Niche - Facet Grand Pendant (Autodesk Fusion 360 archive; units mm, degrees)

design "Facet Grand" references "PCB Single Pendant Canopy"
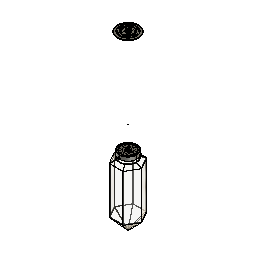
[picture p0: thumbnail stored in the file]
base_feature "Base Feature" bodies "Glass-Facet Grand"
external_derived "ExternalDerived1" bodies "Set Screw", "Strain Relief", "Lead-1", "Lead-2", "Lead-2.1", "Lead-1.1", "Coax", "Stem"
move "Move1"
move "Move2"
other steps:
derived_base_feature "Derived Base Feature" bodies "Set Screw", "Strain Relief", "Lead-1", "Lead-2", "Lead-2.1", "Lead-1.1", "Coax", "Stem"
create_component "CreateComponent1"
named bodies: "Glass-Facet Grand", "Set Screw", "Strain Relief", "Lead-1", "Lead-2", "Lead-2.1", "Lead-1.1", "Coax", "Stem", "Strain Relief Cap", "Nylon Gripper (2)", "Cap", "Thumbscrew (1)", "Thumbscrew (2)", "Thumbscrew (3)", "Niche-PCB", "FJ-Plug Cover", "FJ-Plug", "FJ-Plug1.1", "FJ-Plug1.2", "FJ-Plug1.3", "Fj-Plug1.4", "Canopy", "FJ-Port", "FJ-Port1.1", "Spacer", "Universal Mount", "FJ-Port Cover", "Diffuser"

design "FJ Plug - PCB-Hardware"
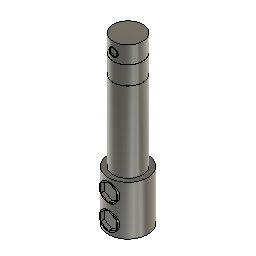
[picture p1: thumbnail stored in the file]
sketch "Sketch1" plane through (0, 0, 0) normal (0, 0, 1) x axis (1, 0, 0)
  circle C1 centre (0, 0) radius 3.048
  point P1 (0, 0)
  point P2 (0, 0)
  coincident P1 P2
  dimension "d1" diameter C1 = 6.096
extrude "Extrude1" new body sketch "Sketch1" along normal blind 34.036
sketch "Sketch2" plane through (0, 0, 0) normal (0, 0, 1) x axis (1, 0, 0)
  circle C1 centre (0, 0) radius 4.064
  point P1 (0, 0)
  point P2 (0, 0)
  coincident P1 P2
  dimension "d4" diameter C1 = 8.128
extrude "Extrude2" add sketch "Sketch2" along normal blind 10.16
sketch "Sketch3" plane through (0, 0, 0) normal (0, 1, 0) x axis (1, 0, 0)
  line L1 (6.35, 0) -> (-6.35, 0)
  line L2 (6.35, -30.48) -> (-6.35, -30.48)
  line L3 (2.54, -30.48) -> (6.35, -30.48)
  line L4 (2.54, -26.67) -> (2.54, -30.48)
  line L5 (6.35, -26.67) -> (2.54, -26.67)
  line L6 (6.35, -30.48) -> (6.35, -26.67)
  horizontal L1
  horizontal L3
  vertical L4
  horizontal L5
  vertical L6
  dimension "d7" = 30.48
revolve "Revolve1" sketch "Sketch3" AlongAngle 360
sketch "Sketch4" plane through (0, 0, 0) normal (0, 1, 0) x axis (1, 0, 0)
  line L1 (2.54, -30.48) -> (3.048, -30.48)
  line L2 (2.54, -26.67) -> (2.54, -30.48)
  line L3 (3.048, -26.67) -> (2.54, -26.67)
  line L4 (3.048, -30.48) -> (3.048, -26.67)
  horizontal L1
  vertical L2
  horizontal L3
  vertical L4
revolve "Revolve2" sketch "Sketch4" AlongAngle 360
chamfer "Chamfer1" distance 0.0254
chamfer "Chamfer2" distance 0.0254
hole "Hole1" HoleDepth 33.401 HoleDiameter 4.826 TipAngle 180
hole "Hole2" HoleDepth 3.81 HoleDiameter 1.778 TipAngle 180
hole "Hole3" HoleDepth 3.81 HoleDiameter 3.81 TipAngle 180
hole "Hole4" HoleDepth 3.81 HoleDiameter 3.81 TipAngle 180
sketch "Sketch5" plane through (0, 0, 0) normal (0, 1, 0) x axis (1, 0, 0)
  circle C1 centre (0, -32.0802) radius 0.889
  dimension "d24" diameter C1 = 1.778
extrude "Extrude3" new body sketch "Sketch5" along normal blind 1.778
move "Move1"
sketch "Sketch6" plane through (0, -3.048, 0) normal (0, -1, 0) x axis (1, 0, 0)
  line L1 (0.7259, 31.6611) -> (0, 31.242)
  line L2 (0.7259, 32.4993) -> (0.7259, 31.6611)
  line L3 (0, 32.9184) -> (0.7259, 32.4993)
  line L4 (-0.7259, 32.4993) -> (0, 32.9184)
  line L5 (-0.7259, 31.6611) -> (-0.7259, 32.4993)
  line L6 (0, 31.242) -> (-0.7259, 31.6611)
  circle C1 centre (0, 32.0802) radius 0.889
  point P2 (0, 32.0802)
  point P9 (0, 32.0802)
  coincident P2 P9
extrude "Extrude4" cut sketch "Sketch6" profile of L1 L2 L3 L4 L5 L6 against normal blind 0.254
sketch "Sketch7" plane through (0, 0, 0) normal (0, 1, 0) x axis (1, 0, 0)
  circle C1 centre (0, -2.4384) radius 1.905
  circle C2 centre (0, -7.5565) radius 1.905
  dimension "d29" diameter C1 = 3.81
  dimension "d30" diameter C2 = 3.81
extrude "Extrude5" new body sketch "Sketch7" profile of C2 along normal blind 3.81
move "Move2"
sketch "Sketch8" plane through (0, -4.064, 0) normal (0, -1, 0) x axis (1, 0, 0)
  line L1 (1.5948, 6.6357) -> (0, 5.715)
  line L2 (1.5948, 8.4772) -> (1.5948, 6.6357)
  line L3 (0, 9.398) -> (1.5948, 8.4772)
  line L4 (-1.5948, 8.4772) -> (0, 9.398)
  line L5 (-1.5948, 6.6357) -> (-1.5948, 8.4772)
  line L6 (0, 5.715) -> (-1.5948, 6.6357)
  circle C1 centre (0, 7.5565) radius 1.905
  point P2 (0, 7.5565)
  point P9 (0, 7.5565)
  coincident P2 P9
extrude "Extrude6" cut sketch "Sketch8" profile of L1 L2 L3 L4 L5 L6 against normal blind 0.762
copy_paste_bodies "CopyPasteBodies2"
move "Move4"
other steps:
base_feature "Base Feature"

design "Flask Petite"
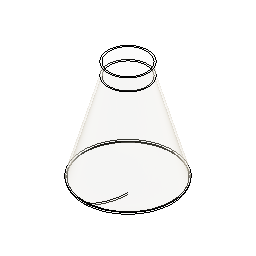
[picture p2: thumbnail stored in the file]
sketch "Sketch1" plane through (0, 0, 0) normal (1, 0, 0) x axis (0, 1, 0)
canvas "Canvas1"
sketch "Sketch2" plane through (0, 0, 0) normal (1, 0, 0) x axis (0, 1, 0)
  line L1 (-5.314, 187.093) -> (-57.384, 187.093)
  line L2 (-57.384, 155.343) -> (-57.384, 187.093)
  line L3 (-121.92, -71.12) -> (-57.384, 155.343)
  line L4 (-5.314, -112.5919) -> (-5.314, 187.093)
  curve K1 (-5.314, -112.5919) -> (-121.92, -74.8854)
  arc A1 centre (-115.3135, -73.0027) radius 6.8695 clockwise from (-121.92, -74.8854) to (-121.92, -71.12)
  point P2 (-57.384, 187.093)
  point P3 (-5.314, 187.093)
  point P4 (-57.384, 155.343)
  horizontal L1
  perpendicular L1 L2
  tangent L3 A1
  perpendicular L1 L4
  dimension "d1" distance P2 P3 = 52.07
  dimension "d2" distance P2 P4 = 31.75
revolve "Revolve1" sketch "Sketch2" AlongAngle 360
fillet "Fillet1" radius 5.08
shell "Shell1" innerThickness 4

design "PCB Single Pendant Canopy" references "Diffuser", "PCB Cap", "Flask Petite", "FJ Cover - PCB-Hardware", "PCB Canopy", "FJ Plug - PCB-Hardware"
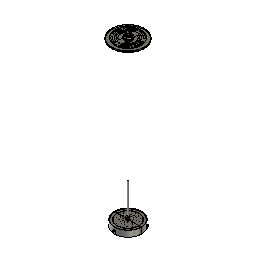
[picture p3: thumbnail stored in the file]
external_derived "ExternalDerived1" bodies "Nylon Gripper", "Set Screw", "Strain Relief", "Lead-1", "Lead-2", "Lead-2.1", "Lead-1.1", "Coax"
external_derived "ExternalDerived2" bodies "FJ-Plug Cover"
move "Move1"
move "Move2" TranslateX 3.175 TranslateY 0.254 TranslateZ 0
move "Move3" TranslateX 0 TranslateY 0 TranslateZ 1092.2
external_derived "ExternalDerived3" bodies "FJ-Plug", "FJ-Plug1.2", "FJ-Plug1.1", "FJ-Plug1.3", "Fj-Plug1.4"
move "Move4" TranslateX 0 TranslateY 0 TranslateZ 1117.6
external_derived "ExternalDerived4" bodies "Nylon Gripper", "Spacer", "Canopy", "FJ-Port", "FJ-Port1.1", "Universal Mount", "FJ-Port Cover", "Lead-1.1"
move "Move5"
move "Move6"
external_derived "ExternalDerived5" bodies "Diffuser"
move "Move7"
external_derived "ExternalDerived6" bodies "Thumbscrew (1)"
align "Align1"
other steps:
derived_base_feature "Derived Base Feature1"
derived_base_feature "Derived Base Feature2" bodies "FJ-Plug Cover"
derived_base_feature "Derived Base Feature3" bodies "FJ-Plug", "FJ-Plug1.1", "FJ-Plug1.2"
derived_base_feature "Derived Base Feature4" bodies "Body1 (1)", "Body1 (1) (1)", "Body2 (1)", "Body1 (2)", "Body1 (3)", "Body1 (4)", "Canopy", "FJ-Port"
derived_base_feature "Derived Base Feature5" bodies "Diffuser"
derived_base_feature "Derived Base Feature6" bodies "Body1", "Thumbscrew (1)"
named bodies: "Nylon Gripper", "Set Screw", "Strain Relief", "Lead-1", "Lead-2", "Lead-2.1", "Lead-1.1", "Coax", "Stem", "stem (2)", "Strain Relief Cap", "Nylon Gripper (2)", "Cap", "Thumbscrew (1)", "Thumbscrew (2)", "Thumbscrew (3)", "Niche-PCB", "FJ-Plug Cover", "FJ-Plug", "FJ-Plug1.1", "FJ-Plug1.2", "FJ-Plug1.3", "Fj-Plug1.4", "Body1 (1)", "Body1 (1) (1)", "Body2 (1)", "Body1 (2)", "Body1 (3)", "Body1 (4)", "Canopy", "FJ-Port", "FJ-Port1.1", "Spacer", "Universal Mount", "FJ-Port Cover", "Diffuser", "Body1"

design "FJ Female"
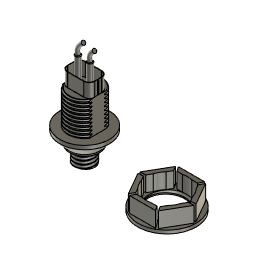
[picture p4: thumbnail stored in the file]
sketch "Sketch1" plane through (0, 0, 0) normal (0, 0, 1) x axis (1, 0, 0)
  circle C1 centre (0, 0) radius 4.445
  point P1 (0, 0)
  point P2 (0, 0)
  coincident P1 P2
  dimension "d1" diameter C1 = 8.89
extrude "Extrude1" new body sketch "Sketch1" along normal blind 6.858
sketch "Sketch2" plane through (0, 0, 6.858) normal (0, 0, 1) x axis (-1, 0, 0)
  circle C1 centre (0, 0) radius 4.445
  circle C2 centre (0, 0) radius 6.985
  point P1 (0, 0)
  point P3 (0, 0)
  coincident P1 P3
  dimension "d4" diameter C2 = 13.97
extrude "Extrude2" add sketch "Sketch2" along normal blind 1.27
work_plane "WorkPlane1" AlongDistance 5.08
sketch "Sketch3" plane through (0, 0, 13.208) normal (0, 0, 1) x axis (1, 0, 0)
  circle C1 centre (0, 0) radius 11.43
  point P1 (0, 0)
  point P2 (0, 0)
  coincident P1 P2
  dimension "d8" diameter C1 = 22.86
loft "Loft1" sketch "Sketch3"
extrude "Extrude3" add of existing geometry blind 1.778
sketch "Sketch4" plane through (0, 0, 14.986) normal (0, 0, 1) x axis (-1, 0, 0)
  circle C1 centre (0, 0) radius 11.43
  circle C2 centre (0, 0) radius 7.62
  point P1 (0, 0)
  point P3 (0, 0)
  coincident P1 P3
  dimension "d11" diameter C2 = 15.24
extrude "Extrude4" add sketch "Sketch4" profile of C2 along normal blind 15.24
sketch "Sketch5" plane through (0, 0, 30.226) normal (0, 0, 1) x axis (-1, 0, 0)
  line L1 (6.35, 0) -> (0, 0)
  line L2 (-6.35, 0) -> (0, 0)
  line L3 (6.35, -4.2121) -> (6.35, 0)
  line L4 (6.35, 4.2121) -> (6.35, 0)
  line L5 (-6.35, -4.2121) -> (-6.35, 0)
  line L6 (-6.35, 4.2121) -> (-6.35, 0)
  circle C1 centre (0, 0) radius 7.62
  point P2 (0, 0)
  point P3 (0, 0)
  point P5 (0, 0)
  point P7 (6.35, -4.2121)
  point P8 (6.35, 4.2121)
  point P9 (-6.35, -4.2121)
  point P10 (-6.35, 0)
  point P11 (-6.35, 4.2121)
  point P4 (6.35, 0)
  point P6 (-6.35, 0)
  coincident P2 P3
  horizontal L1
  coincident P2 P5
  parallel L1 L2
  coincident C1 P7
  perpendicular L1 L3
  coincident C1 P8
  perpendicular L1 L4
  coincident C1 P9
  perpendicular L2 L5
  coincident L2 P10
  perpendicular L2 L6
  coincident C1 P11
  dimension "d14" distance P3 P4 = 6.35
  dimension "d15" distance P5 P6 = 6.35
extrude "Extrude5" cut sketch "Sketch5" profile of C1 L3 L4 L5 L6 against normal blind 15.24
sketch "Sketch6" plane through (0, 0, 30.226) normal (0, 0, 1) x axis (-1, 0, 0)
  line L1 (-6.35, -4.2121) -> (-6.35, 4.2121)
  line L2 (6.35, 4.2121) -> (6.35, -4.2121)
  line L3 (-6.35, -4.2121) -> (6.35, -4.2121)
  line L4 (6.35, 4.2121) -> (-6.35, 4.2121)
  line L5 (6.35, -4.2121) -> (6.35, 4.2121)
  line L6 (-6.35, 4.2121) -> (-6.35, -4.2121)
  line L7 (-6.223, 4.064) -> (6.223, 4.064)
  line L8 (-6.223, -4.064) -> (-6.223, 4.064)
  line L9 (6.223, -4.064) -> (-6.223, -4.064)
  line L10 (6.223, 4.064) -> (6.223, -4.064)
  line L11 (-6.223, -4.064) -> (6.223, 4.064)
  line L12 (6.223, -4.064) -> (-6.223, 4.064)
  arc A1 centre (0, 0) radius 7.62 clockwise from (6.35, -4.2121) to (-6.35, -4.2121)
  arc A2 centre (0, 0) radius 7.62 clockwise from (-6.35, 4.2121) to (6.35, 4.2121)
  point P4 (6.35, -4.2121)
  point P7 (6.35, -4.2121)
  point P3 (-6.35, -4.2121)
  point P8 (-6.35, -4.2121)
  point P2 (-6.35, 4.2121)
  point P9 (-6.35, 4.2121)
  point P6 (6.35, 4.2121)
  point P10 (6.35, 4.2121)
  point P15 (0, 0)
  point P5 (0, 0)
  point P13 (-6.223, -4.064)
  point P14 (6.223, -4.064)
  point P12 (-6.223, 4.064)
  coincident P4 P7
  coincident P3 P8
  coincident P2 P9
  coincident P6 P10
  perpendicular L7 L8
  parallel L7 L9
  parallel L8 L10
  horizontal L7
  coincident L11 P15
  coincident L12 P15
  coincident P5 P15
  dimension "d18" distance P13 P14 = 12.446
  dimension "d19" distance P12 P13 = 8.128
extrude "Extrude6" add sketch "Sketch6" profile of L1 L2 L3 L4 L5 L6 L7 L8 L9 L10 along normal blind 6.35
fillet "Fillet1" radius 2.54
sketch "Sketch7" plane through (6.35, 0, 0) normal (1, 0, 0) x axis (0, 1, 0)
  line L1 (1.6721, 36.576) -> (1.6721, 30.226)
  line L2 (-1.6721, 36.576) -> (1.6721, 36.576)
  line L3 (-1.6721, 30.226) -> (-1.6721, 36.576)
  line L4 (-4.2121, 30.226) -> (-1.6721, 30.226)
  line L5 (-4.2121, 14.986) -> (-4.2121, 30.226)
  line L6 (4.2121, 14.986) -> (-4.2121, 14.986)
  line L7 (4.2121, 30.226) -> (4.2121, 14.986)
  line L8 (1.6721, 30.226) -> (4.2121, 30.226)
  line L9 (0.254, 36.576) -> (-0.2492, 36.576)
  line L10 (0.254, 30.226) -> (0.254, 36.576)
  line L11 (-0.2492, 30.226) -> (0.254, 30.226)
  line L12 (-0.2492, 36.576) -> (-0.2492, 30.226)
  point P10 (-0.2492, 36.576)
  horizontal L9
  vertical L10
  horizontal L11
  vertical L12
  coincident L2 P10
extrude "Extrude7" cut sketch "Sketch7" profile of L2 L9 L10 L11 L12 against normal blind 0.508
thread "Thread1"
fillet "Fillet2" radius 0.635
thread "Thread2"
sketch "Sketch8" plane through (0, 0, 30.226) normal (0, 0, 1) x axis (-1, 0, 0)
  line L1 (-6.223, -1.524) -> (-6.223, -0.254)
  line L2 (3.683, -4.064) -> (-3.683, -4.064)
  line L3 (6.223, 1.524) -> (6.223, -1.524)
  line L4 (-3.683, 4.064) -> (3.683, 4.064)
  line L5 (-6.223, 0.2492) -> (-6.223, 1.524)
  line L6 (-6.35, 0.2492) -> (-6.223, 0.2492)
  line L7 (-6.35, -0.254) -> (-6.35, 0.2492)
  line L8 (-6.223, -0.254) -> (-6.35, -0.254)
  arc A1 centre (-3.683, -1.524) radius 2.54 clockwise from (-3.683, -4.064) to (-6.223, -1.524)
  arc A2 centre (3.683, -1.524) radius 2.54 clockwise from (6.223, -1.524) to (3.683, -4.064)
  arc A3 centre (3.683, 1.524) radius 2.54 clockwise from (3.683, 4.064) to (6.223, 1.524)
  arc A4 centre (-3.683, 1.524) radius 2.54 clockwise from (-6.223, 1.524) to (-3.683, 4.064)
  circle C1 centre (3.048, 0) radius 1.27
  circle C2 centre (-2.54, 0) radius 1.27
  dimension "d26" diameter C1 = 2.54
  dimension "d27" diameter C2 = 2.54
extrude "Extrude8" add sketch "Sketch8" profile of C1 C2 along normal blind 11.43
sketch "Sketch9" plane through (0, 0, 0) normal (0, 1, 0) x axis (1, 0, 0)
  curve K1 (4.572, -46.99) -> (2.54, -41.656)
  curve K2 (-0.508, -47.752) -> (-3.048, -41.656)
pipe "Pipe1" SectionSize 1.778 SectionThickness 0.0762
pipe "Pipe2" SectionSize 1.778 SectionThickness 0.0762
sketch "Sketch10" plane through (0, 0, 0) normal (0, 0, 1) x axis (1, 0, 0)
  circle C1 centre (38.1, 0) radius 13.462
  dimension "d38" diameter C1 = 26.924
extrude "Extrude9" new body sketch "Sketch10" along normal blind 1.524
sketch "Sketch11" plane through (0, 0, 1.524) normal (0, 0, 1) x axis (-1, 0, 0)
  circle C1 centre (-38.1, 0) radius 13.462
  circle C2 centre (-38.1, 0) radius 9.271
  concentric C1 C2
  dimension "d41" diameter C2 = 18.542
extrude "Extrude10" cut sketch "Sketch11" profile of C2 against normal blind 7.62
sketch "Sketch12" plane through (0, 0, 1.524) normal (0, 0, 1) x axis (-1, 0, 0)
  line L1 (-24.9018, 0) -> (-31.5009, -11.43)
  line L2 (-31.5009, 11.43) -> (-24.9018, 0)
  line L3 (-44.6991, 11.43) -> (-31.5009, 11.43)
  line L4 (-51.2982, 0) -> (-44.6991, 11.43)
  line L5 (-44.6991, -11.43) -> (-51.2982, 0)
  line L6 (-31.5009, -11.43) -> (-44.6991, -11.43)
  line L7 (-27.3948, 0) -> (-32.7474, -9.271)
  line L8 (-32.7474, 9.271) -> (-27.3948, 0)
  line L9 (-43.4526, 9.271) -> (-32.7474, 9.271)
  line L10 (-48.8052, 0) -> (-43.4526, 9.271)
  line L11 (-43.4526, -9.271) -> (-48.8052, 0)
  line L12 (-32.7474, -9.271) -> (-43.4526, -9.271)
  circle C1 centre (-38.1, 0) radius 9.271
  circle C2 centre (-38.1, 0) radius 13.462
  point P2 (-38.1, 0)
  point P9 (-38.1, 0)
  point P16 (-38.1, 0)
  coincident P2 P9
  coincident P9 P16
extrude "Extrude11" add sketch "Sketch12" profile of L1 L2 L3 L4 L5 L6 L7 L8 L9 L10 L11 L12 along normal blind 7.112
thread "Thread3"
sketch "Sketch13" plane through (0, 0, 8.636) normal (0, 0, 1) x axis (-1, 0, 0)
  line L1 (-43.4526, -9.271) -> (-32.7474, -9.271)
  line L2 (-48.8052, 0) -> (-43.4526, -9.271)
  line L3 (-43.4526, 9.271) -> (-48.8052, 0)
  line L4 (-32.7474, 9.271) -> (-43.4526, 9.271)
  line L5 (-27.3948, 0) -> (-32.7474, 9.271)
  line L6 (-32.7474, -9.271) -> (-27.3948, 0)
  line L7 (-31.5009, -11.43) -> (-44.6991, -11.43)
  line L8 (-24.9018, 0) -> (-31.5009, -11.43)
  line L9 (-31.5009, 11.43) -> (-24.9018, 0)
  line L10 (-44.6991, 11.43) -> (-31.5009, 11.43)
  line L11 (-51.2982, 0) -> (-44.6991, 11.43)
  line L12 (-44.6991, -11.43) -> (-51.2982, 0)
sketch "Sketch14" plane through (0, 0, 8.636) normal (0, 0, 1) x axis (-1, 0, 0)
  circle C1 centre (-38.1, 0) radius 9.525
  dimension "d46" diameter C1 = 19.05
extrude "Extrude12" cut sketch "Sketch14" against normal blind 7.112
sketch "Sketch15" plane through (0, 0, 8.636) normal (0, 0, 1) x axis (-1, 0, 0)
  line L1 (-51.2982, 0) -> (-44.6991, 11.43)
  line L2 (-43.4526, 9.271) -> (-48.8052, 0)
  line L3 (-32.7474, 9.271) -> (-43.4526, 9.271)
  line L4 (-44.6991, 11.43) -> (-31.5009, 11.43)
  line L5 (-44.1911, 11.43) -> (-42.7995, 9.271)
  line L6 (-40.2139, 9.271) -> (-42.7995, 9.271)
  line L7 (-43.7181, 8.8112) -> (-45.0232, 10.8687)
  line L8 (-43.4526, 9.271) -> (-42.7995, 9.271)
  line L9 (-43.7181, 8.8112) -> (-43.4526, 9.271)
  line L10 (-45.0232, 10.8687) -> (-44.6991, 11.43)
  line L11 (-44.1911, 11.43) -> (-44.6991, 11.43)
  line L12 (-48.5398, -0.4598) -> (-50.9742, -0.5613)
  line L13 (-48.5398, -0.4598) -> (-48.8052, 0)
  line L14 (-48.8052, 0) -> (-48.4787, 0.5657)
  line L15 (-51.0442, 0.4399) -> (-48.4787, 0.5657)
  line L16 (-51.0442, 0.4399) -> (-51.2982, 0)
  line L17 (-50.9742, -0.5613) -> (-51.2982, 0)
  line L18 (-42.9217, -9.271) -> (-44.051, -11.43)
  line L19 (-42.9217, -9.271) -> (-43.4526, -9.271)
  line L20 (-43.4526, -9.271) -> (-43.7792, -8.7053)
  line L21 (-44.9531, -10.9901) -> (-43.7792, -8.7053)
  line L22 (-44.9531, -10.9901) -> (-44.6991, -11.43)
  line L23 (-44.051, -11.43) -> (-44.6991, -11.43)
  line L24 (-32.4819, -8.8112) -> (-31.1768, -10.8687)
  line L25 (-32.4819, -8.8112) -> (-32.7474, -9.271)
  line L26 (-32.7474, -9.271) -> (-33.4005, -9.271)
  line L27 (-32.0089, -11.43) -> (-33.4005, -9.271)
  line L28 (-32.0089, -11.43) -> (-31.5009, -11.43)
  line L29 (-31.1768, -10.8687) -> (-31.5009, -11.43)
  line L30 (-27.6603, 0.4598) -> (-25.2258, 0.5613)
  line L31 (-27.6603, 0.4598) -> (-27.3948, 0)
  line L32 (-27.3948, 0) -> (-27.7214, -0.5657)
  line L33 (-25.1558, -0.4399) -> (-27.7214, -0.5657)
  line L34 (-25.1558, -0.4399) -> (-24.9018, 0)
  line L35 (-25.2258, 0.5613) -> (-24.9018, 0)
  line L36 (-33.2783, 9.271) -> (-32.149, 11.43)
  line L37 (-33.2783, 9.271) -> (-32.7474, 9.271)
  line L38 (-32.7474, 9.271) -> (-32.4208, 8.7053)
  line L39 (-31.2469, 10.9901) -> (-32.4208, 8.7053)
  line L40 (-31.2469, 10.9901) -> (-31.5009, 11.43)
  line L41 (-32.149, 11.43) -> (-31.5009, 11.43)
  point P10 (-42.7995, 9.271)
  point P12 (-45.0232, 10.8687)
  point P13 (-43.7181, 8.8112)
  point P5 (-43.4526, 9.271)
  point P14 (-43.4526, 9.271)
  point P16 (-44.1911, 11.43)
  point P9 (-44.6991, 11.43)
  point P15 (-44.6991, 11.43)
  horizontal L6
  coincident L3 P10
  coincident L1 P12
  coincident L2 P13
  coincident P5 P14
  coincident L4 P16
  coincident P9 P15
  coincident L4 P16
  dimension "d50" distance P15 P16 = 0.508
  dimension "d54" C-Pattern1-Angle = 360
extrude "Extrude13" cut sketch "Sketch15" profile of L1 L2 L3 L4 L5 L7 L8 L9 L10 L11 L12 L13 L14 L15 L16 L17 L18 L19 L20 L21 L22 L23 L24 L25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 against normal blind 7.112

design "FJ Cover - PCB-Hardware"
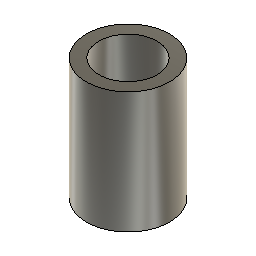
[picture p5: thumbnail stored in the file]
sketch "Sketch1" plane through (0, 0, 0) normal (0, 0, 1) x axis (1, 0, 0)
  circle C1 centre (0, 0) radius 6.35
  point P1 (0, 0)
  point P2 (0, 0)
  coincident P1 P2
  dimension "d1" diameter C1 = 12.7
extrude "Extrude1" new body sketch "Sketch1" along normal blind 18.542
hole "Hole1" HoleDepth 13.97 HoleDiameter 8.89 TipAngle 180
hole "Hole2" HoleDepth 13.97 HoleDiameter 3.556 TipAngle 180

design "PCB Canopy" references "Port Cover - PCB-Hardware", "FJ Female", "Canopy - PCB-Hardware", "Universal Mounting Bracket - PCB-Hardware", "FJ Cover - PCB-Hardware", "Spacer - PCB-Hardware"
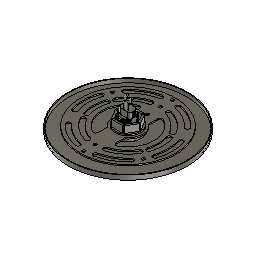
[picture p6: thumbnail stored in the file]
external_derived "ExternalDerived"
external_derived "ExternalDerived"
external_derived "ExternalDerived3" bodies "Body1 (1)"
external_derived "ExternalDerived4"
external_derived "ExternalDerived5"
move "Move1"
move "Move2"
move "Move3"
move "Move4"
move "Move5"
move "Move6"
move "Move7"
move "Move8"
external_derived "ExternalDerived6"
align "Align1"
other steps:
derived_base_feature "Derived Base Feature" bodies "Body1"
derived_base_feature "Derived Base Feature" bodies "Body1 (1)", "Body2"
derived_base_feature "Derived Base Feature3" bodies "Body1 (2)", "Body1 (1)"
derived_base_feature "Derived Base Feature4" bodies "Body1 (3)"
derived_base_feature "Derived Base Feature5" bodies "Body1 (4)"
derived_base_feature "Derived Base Feature6" bodies "Body1 (5)"
named bodies: "Body1", "Body1 (1)", "Body2", "Body1 (2)", "Body1 (3)", "Body1 (4)", "Body1 (5)"

design "Spacer - PCB-Hardware"
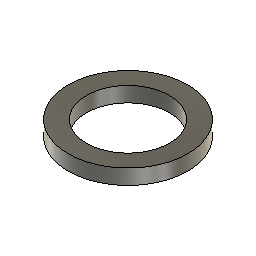
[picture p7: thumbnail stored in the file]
sketch "Sketch1" plane through (0, 0, 0) normal (0, 0, 1) x axis (1, 0, 0)
  circle C1 centre (0, 0) radius 14.097
  circle C2 centre (0, 0) radius 9.779
  point P1 (0, 0)
  point P2 (0, 0)
  point P3 (0, 0)
  coincident P1 P2
  coincident P1 P3
  dimension "d1" diameter C1 = 28.194
  dimension "d2" diameter C2 = 19.558
extrude "Extrude1" new body sketch "Sketch1" along normal blind 3.556

design "Universal Mounting Bracket - PCB-Hardware"
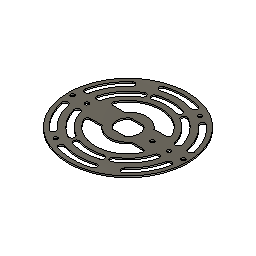
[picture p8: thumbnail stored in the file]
sketch "Sketch1" plane through (0, 0, 0) normal (0, 0, 1) x axis (1, 0, 0)
  circle C1 centre (0, 0) radius 50.8
  arc A1 centre (0, 0) radius 42.545 clockwise from (-13.1471, 40.4627) to (13.1471, 40.4627)
  arc A2 centre (0, 0) radius 47.371 clockwise from (-14.6384, 45.0525) to (14.6384, 45.0525)
  arc A3 centre (-13.8928, 42.7576) radius 2.413 clockwise from (-13.1471, 40.4627) to (-14.6384, 45.0525)
  arc A4 centre (13.8928, 42.7576) radius 2.413 clockwise from (14.6384, 45.0525) to (13.1471, 40.4627)
  arc A5 centre (0, 0) radius 47.371 clockwise from (-46.3358, 9.849) to (-31.6974, 35.2035)
  arc A6 centre (0, 0) radius 42.545 clockwise from (-41.6153, 8.8456) to (-28.4682, 31.6171)
  arc A7 centre (-43.9756, 9.3473) radius 2.413 clockwise from (-41.6153, 8.8456) to (-46.3358, 9.849)
  arc A8 centre (-30.0828, 33.4103) radius 2.413 clockwise from (-31.6974, 35.2035) to (-28.4682, 31.6171)
  arc A9 centre (0, 0) radius 47.371 clockwise from (-31.6974, -35.2035) to (-46.3358, -9.849)
  arc A10 centre (0, 0) radius 42.545 clockwise from (-28.4682, -31.6171) to (-41.6153, -8.8456)
  arc A11 centre (-30.0828, -33.4103) radius 2.413 clockwise from (-28.4682, -31.6171) to (-31.6974, -35.2035)
  arc A12 centre (-43.9756, -9.3473) radius 2.413 clockwise from (-46.3358, -9.849) to (-41.6153, -8.8456)
  arc A13 centre (0, 0) radius 47.371 clockwise from (14.6384, -45.0525) to (-14.6384, -45.0525)
  arc A14 centre (0, 0) radius 42.545 clockwise from (13.1471, -40.4627) to (-13.1471, -40.4627)
  arc A15 centre (13.8928, -42.7576) radius 2.413 clockwise from (13.1471, -40.4627) to (14.6384, -45.0525)
  arc A16 centre (-13.8928, -42.7576) radius 2.413 clockwise from (-14.6384, -45.0525) to (-13.1471, -40.4627)
  arc A17 centre (0, 0) radius 47.371 clockwise from (46.3358, -9.849) to (31.6974, -35.2035)
  arc A18 centre (0, 0) radius 42.545 clockwise from (41.6153, -8.8456) to (28.4682, -31.6171)
  arc A19 centre (43.9756, -9.3473) radius 2.413 clockwise from (41.6153, -8.8456) to (46.3358, -9.849)
  arc A20 centre (30.0828, -33.4103) radius 2.413 clockwise from (31.6974, -35.2035) to (28.4682, -31.6171)
  arc A21 centre (0, 0) radius 47.371 clockwise from (31.6974, 35.2035) to (46.3358, 9.849)
  arc A22 centre (0, 0) radius 42.545 clockwise from (28.4682, 31.6171) to (41.6153, 8.8456)
  arc A23 centre (30.0828, 33.4103) radius 2.413 clockwise from (28.4682, 31.6171) to (31.6974, 35.2035)
  arc A24 centre (43.9756, 9.3473) radius 2.413 clockwise from (46.3358, 9.849) to (41.6153, 8.8456)
  arc A25 centre (0, 0) radius 32.385 clockwise from (-31.2224, 8.5995) to (-16.1925, 28.0462)
  arc A26 centre (0, 0) radius 37.338 clockwise from (-35.9514, 10.0809) to (-18.669, 32.3357)
  arc A27 centre (0, 0) radius 32.385 clockwise from (16.1925, 28.0462) to (31.2224, 8.5995)
  arc A28 centre (0, 0) radius 32.385 clockwise from (-10.0075, 30.8) to (10.0075, 30.8)
  arc A29 centre (0, 0) radius 37.338 clockwise from (18.669, 32.3357) to (35.9514, 10.0809)
  arc A30 centre (0, 0) radius 37.338 clockwise from (-11.5381, 35.5105) to (11.5381, 35.5105)
  arc A31 centre (-33.5467, 9.4685) radius 2.4814 clockwise from (-31.1111, 8.9939) to (-35.9167, 10.2037)
  arc A32 centre (-17.4307, 30.1909) radius 2.4765 clockwise from (-18.669, 32.3357) to (-16.1925, 28.0462)
  arc A33 centre (-10.7728, 33.1553) radius 2.4765 clockwise from (-10.0075, 30.8) to (-11.5381, 35.5105)
  arc A34 centre (10.7728, 33.1553) radius 2.4765 clockwise from (11.5381, 35.5105) to (10.0075, 30.8)
  arc A35 centre (17.4307, 30.1909) radius 2.4765 clockwise from (16.1925, 28.0462) to (18.669, 32.3357)
  arc A36 centre (33.5467, 9.4685) radius 2.4814 clockwise from (35.9167, 10.2037) to (31.1111, 8.9939)
  arc A37 centre (-33.5467, -9.4685) radius 2.4814 clockwise from (-35.9167, -10.2037) to (-31.1111, -8.9939)
  arc A38 centre (0, 0) radius 37.338 clockwise from (-18.669, -32.3357) to (-35.9514, -10.0809)
  arc A39 centre (0, 0) radius 32.385 clockwise from (-16.1925, -28.0462) to (-31.2224, -8.5995)
  arc A40 centre (-17.4307, -30.1909) radius 2.4765 clockwise from (-16.1925, -28.0462) to (-18.669, -32.3357)
  arc A41 centre (-10.7728, -33.1553) radius 2.4765 clockwise from (-11.5381, -35.5105) to (-10.0075, -30.8)
  arc A42 centre (0, 0) radius 37.338 clockwise from (11.5381, -35.5105) to (-11.5381, -35.5105)
  arc A43 centre (0, 0) radius 32.385 clockwise from (10.0075, -30.8) to (-10.0075, -30.8)
  arc A44 centre (10.7728, -33.1553) radius 2.4765 clockwise from (10.0075, -30.8) to (11.5381, -35.5105)
  arc A45 centre (17.4307, -30.1909) radius 2.4765 clockwise from (18.669, -32.3357) to (16.1925, -28.0462)
  arc A46 centre (0, 0) radius 37.338 clockwise from (35.9514, -10.0809) to (18.669, -32.3357)
  arc A47 centre (0, 0) radius 32.385 clockwise from (31.2224, -8.5995) to (16.1925, -28.0462)
  arc A48 centre (33.5467, -9.4685) radius 2.4814 clockwise from (31.1111, -8.9939) to (35.9167, -10.2037)
  point P1 (0, 0)
  point P2 (0, 0)
  point P71 (-35.9514, 10.0809)
  point P72 (-31.2224, 8.5995)
  point P73 (35.9514, 10.0809)
  point P74 (31.2224, 8.5995)
  point P75 (-31.1111, 8.9939)
  point P76 (-35.9167, 10.2037)
  point P77 (35.9167, 10.2037)
  point P78 (31.1111, 8.9939)
  coincident P1 P2
  concentric C1 A2
  concentric A1 A2
  concentric A17 A26
  concentric A25 A26
  concentric A25 A27
  concentric A26 A29
  concentric A27 A28
  concentric A29 A30
  coincident P71 A31
  coincident P72 A31
  coincident P73 A36
  coincident P74 A36
  coincident A25 P75
  coincident A26 P76
  coincident A29 P77
  coincident A27 P78
  dimension "d1" diameter C1 = 101.6
  dimension "d2" diameter A2 = 94.742
  dimension "d11" diameter A26 = 74.676
  dimension "d12" diameter A25 = 64.77
  dimension "d10" C-Pattern1-Angle = 360
sketch "Sketch2" plane through (0, 0, 0) normal (0, 0, 1) x axis (1, 0, 0)
  line L1 (5.3986, -8.001) -> (-5.3986, -8.001)
  line L2 (5.3986, 8.001) -> (-5.3986, 8.001)
  arc A1 centre (0, 0) radius 9.652 clockwise from (-5.3986, -8.001) to (-5.3986, 8.001)
  arc A2 centre (0, 0) radius 9.652 clockwise from (5.3986, 8.001) to (5.3986, -8.001)
  point P1 (0, 0)
  point P2 (0, 0)
  coincident P1 P2
  concentric A1 A2
  dimension "d6" diameter A1 = 19.304
sketch "Sketch3" plane through (0, 0, 0) normal (0, 0, 1) x axis (1, 0, 0)
  line L1 (-12.5409, 9.525) -> (-22.2072, 9.525)
  line L2 (22.2072, 9.525) -> (12.5409, 9.525)
  line L3 (-12.5409, -9.525) -> (-22.2072, -9.525)
  line L4 (22.2072, -9.525) -> (12.5409, -9.525)
  arc A1 centre (0, 0) radius 15.748 clockwise from (12.5409, -9.525) to (-12.5409, -9.525)
  arc A2 centre (0, 0) radius 15.748 clockwise from (-12.5409, 9.525) to (12.5409, 9.525)
  arc A3 centre (0, 0) radius 27.813 clockwise from (24.4391, -13.2776) to (-24.4391, -13.2776)
  arc A4 centre (0, 0) radius 27.813 clockwise from (-24.4391, 13.2776) to (24.4391, 13.2776)
  arc A5 centre (-22.2072, 12.065) radius 2.54 clockwise from (-22.2072, 9.525) to (-24.4391, 13.2776)
  arc A6 centre (22.2072, 12.065) radius 2.54 clockwise from (24.4391, 13.2776) to (22.2072, 9.525)
  arc A7 centre (-22.2072, -12.065) radius 2.54 clockwise from (-24.4391, -13.2776) to (-22.2072, -9.525)
  arc A8 centre (22.2072, -12.065) radius 2.54 clockwise from (22.2072, -9.525) to (24.4391, -13.2776)
  point P1 (0, 0)
  point P2 (0, 0)
  point P5 (12.5409, 9.525)
  coincident P1 P2
  concentric A1 A3
  coincident P5 A1
  collinear L1 L2
  collinear L3 L4
  concentric A1 A2
  concentric A3 A4
  tangent L1 A5
  tangent A4 A5
  tangent L2 A6
  tangent A4 A6
  equal A5 A6
  tangent L3 A7
  tangent A3 A7
  equal A5 A7
  tangent L4 A8
  tangent A3 A8
  equal A5 A8
  dimension "d17" diameter A3 = 55.626
  dimension "d18" diameter A1 = 31.496
  dimension "d37" radius A5 = 2.54
sketch "Sketch4" plane through (0, 0, 0) normal (0, 0, 1) x axis (1, 0, 0)
  circle C1 centre (22.479, 38.9348) radius 1.651
  circle C2 centre (-22.479, -38.9348) radius 1.651
  circle C3 centre (-34.8615, 0) radius 1.651
  circle C4 centre (-47.117, 0) radius 1.651
  circle C5 centre (34.8615, 0) radius 1.651
  circle C6 centre (47.117, 0) radius 1.651
  circle C7 centre (20.701, 0) radius 1.651
  dimension "d36" diameter C7 = 3.302
  dimension "d25" C-Pattern2-Angle = 180
extrude "Extrude1" new body sketch "Sketch1" profile of C1 A2 A1 A3 A4 A5 A6 A7 A8 A9 A10 A11 A12 A13 A14 A15 A16 A17 A18 A19 A20 A21 A22 A23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 along normal blind 1.27
extrude "Extrude2" cut sketch "Sketch3" + "Sketch2" profile of S2:A2 S2:L1 S2:L2 S1:A4 S1:A2 S1:L4 S1:L2 S1:A5 S1:A6 S1:A7 S1:A8 blind 1.27
extrude "Extrude3" cut sketch "Sketch4" along normal blind 1.27

design "Port Cover - PCB-Hardware"
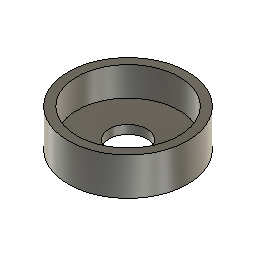
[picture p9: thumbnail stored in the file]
sketch "Sketch1" plane through (0, 0, 0) normal (0, 0, 1) x axis (1, 0, 0)
  circle C1 centre (0, 0) radius 14.097
  point P1 (0, 0)
  point P2 (0, 0)
  coincident P1 P2
  dimension "d1" diameter C1 = 28.194
extrude "Extrude1" new body sketch "Sketch1" along normal blind 8.89
shell "Shell1" innerThickness 2.032
hole "Hole1" HoleDepth 22.86 HoleDiameter 8.89 TipAngle 118

design "PCB Cap"
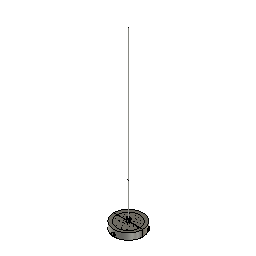
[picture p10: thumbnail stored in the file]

design "Canopy - PCB-Hardware"
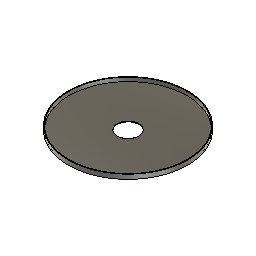
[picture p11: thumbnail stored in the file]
sketch "Sketch1" plane through (0, 0, 0) normal (0, 0, 1) x axis (1, 0, 0)
  circle C1 centre (0, 0) radius 63.5
  point P1 (0, 0)
  point P2 (0, 0)
  coincident P1 P2
extrude "Extrude1" new body sketch "Sketch1" along normal blind 4.826
shell "Shell1" innerThickness 0.762
hole "Hole1" HoleDepth 22.86 HoleDiameter 22.86 TipAngle 118

design "Diffuser"
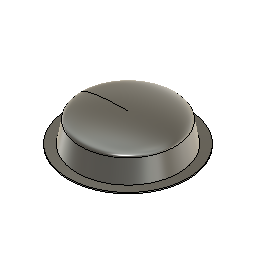
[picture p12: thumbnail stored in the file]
sketch "Sketch1" plane through (0, 0, 0) normal (0, 1, 0) x axis (1, 0, 0)
sketch "Sketch2" plane through (0, 0, 0) normal (0, 0, 1) x axis (1, 0, 0)
  circle C1 centre (0, 0) radius 43.18
  point P1 (0, 0)
  point P2 (0, 0)
  coincident P1 P2
  dimension "d1" diameter C1 = 86.36
sketch "Sketch4" plane through (0, 0, 0) normal (0, 0, 1) x axis (1, 0, 0)
  circle C1 centre (0, 0) radius 50.8
  point P1 (0, 0)
  point P2 (0, 0)
  coincident P1 P2
  dimension "d2" diameter C1 = 101.6
extrude "Extrude1" new body sketch "Sketch4" along normal blind 1.016
sketch "Sketch5" plane through (0, 0, 1.016) normal (0, 0, 1) x axis (-1, 0, 0)
  circle C1 centre (0, 0) radius 50.8
  circle C2 centre (0, 0) radius 42.545
  concentric C1 C2
  dimension "d5" diameter C2 = 85.09
sketch "Sketch8" plane through (0, 0, 1.016) normal (0, 0, 1) x axis (-1, 0, 0)
  circle C1 centre (0, 0) radius 42.545
sketch "Sketch11" plane through (0, 0, 0) normal (0, 1, 0) x axis (1, 0, 0)
sketch "Sketch14" plane through (0, 0, 0) normal (0, 1, 0) x axis (1, 0, 0)
sketch "Sketch15" plane through (0, 0, 1.016) normal (0, 0, 1) x axis (-1, 0, 0)
  line L1 (-42.545, 0) -> (0, 0)
  circle C1 centre (0, 0) radius 42.545
  point P1 (0, 0)
  point P3 (0, 0)
  point P4 (-42.545, 0)
  coincident P1 P3
  coincident C1 P4
  horizontal L1
sketch "Sketch16" plane through (0, 0, 0) normal (0, 0, -1) x axis (1, 0, 0)
  circle C1 centre (0, 0) radius 50.8
sketch "Sketch17" plane through (0, 0, 0) normal (0, 1, 0) x axis (1, 0, 0)
  line L1 (0, -18.8361) -> (40.0012, -18.8361)
  line L2 (0, -1.016) -> (43.18, -1.016)
  line L3 (40.0012, -18.8361) -> (43.18, -1.016)
  line L4 (0, -1.016) -> (0, -25.146)
  line L5 (0, -1.016) -> (43.18, -1.016)
  line L6 (0, -25.1861) -> (0, -1.016)
  curve K1 (0, -25.1861) -> (0, -12.4861)
  curve K2 (40.0012, -18.8361) -> (-40.0012, -18.8361)
  line L7 (0, -12.4861) -> (0, -25.146)
  closed curve K3 centre (0, -18.8361)
  point P3 (0, -1.016)
  point P6 (0, -1.016)
  point P9 (0, -1.016)
  point P10 (0, -1.016)
  point P8 (0, -12.4861)
  point P7 (0, -25.1861)
  point P14 (-40.0012, -18.8361)
  point P11 (40.0012, -18.8361)
  point P4 (43.18, -1.016)
  coincident P3 P6
  coincident P3 P9
  perpendicular L2 L4
  coincident P3 P10
  perpendicular L5 L6
  horizontal L1
  perpendicular L1 K1
  coincident P8 K3
  coincident P7 K3
  coincident K3 P14
  coincident P11 K3
  parallel K1 L7
  dimension "d17" distance P3 P4 = 43.18
revolve "Revolve4" sketch "Sketch17" AlongAngle 360
shell "Shell5" innerThickness 1.016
